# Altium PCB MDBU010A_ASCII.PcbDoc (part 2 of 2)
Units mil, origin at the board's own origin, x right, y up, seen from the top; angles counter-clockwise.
Board outline 3300 x 2500 mil, 2 copper layers (Top Layer, Bottom Layer), stack 64.8 mil thick; 105 components, 70 nets, 307 pads, 460 vias.
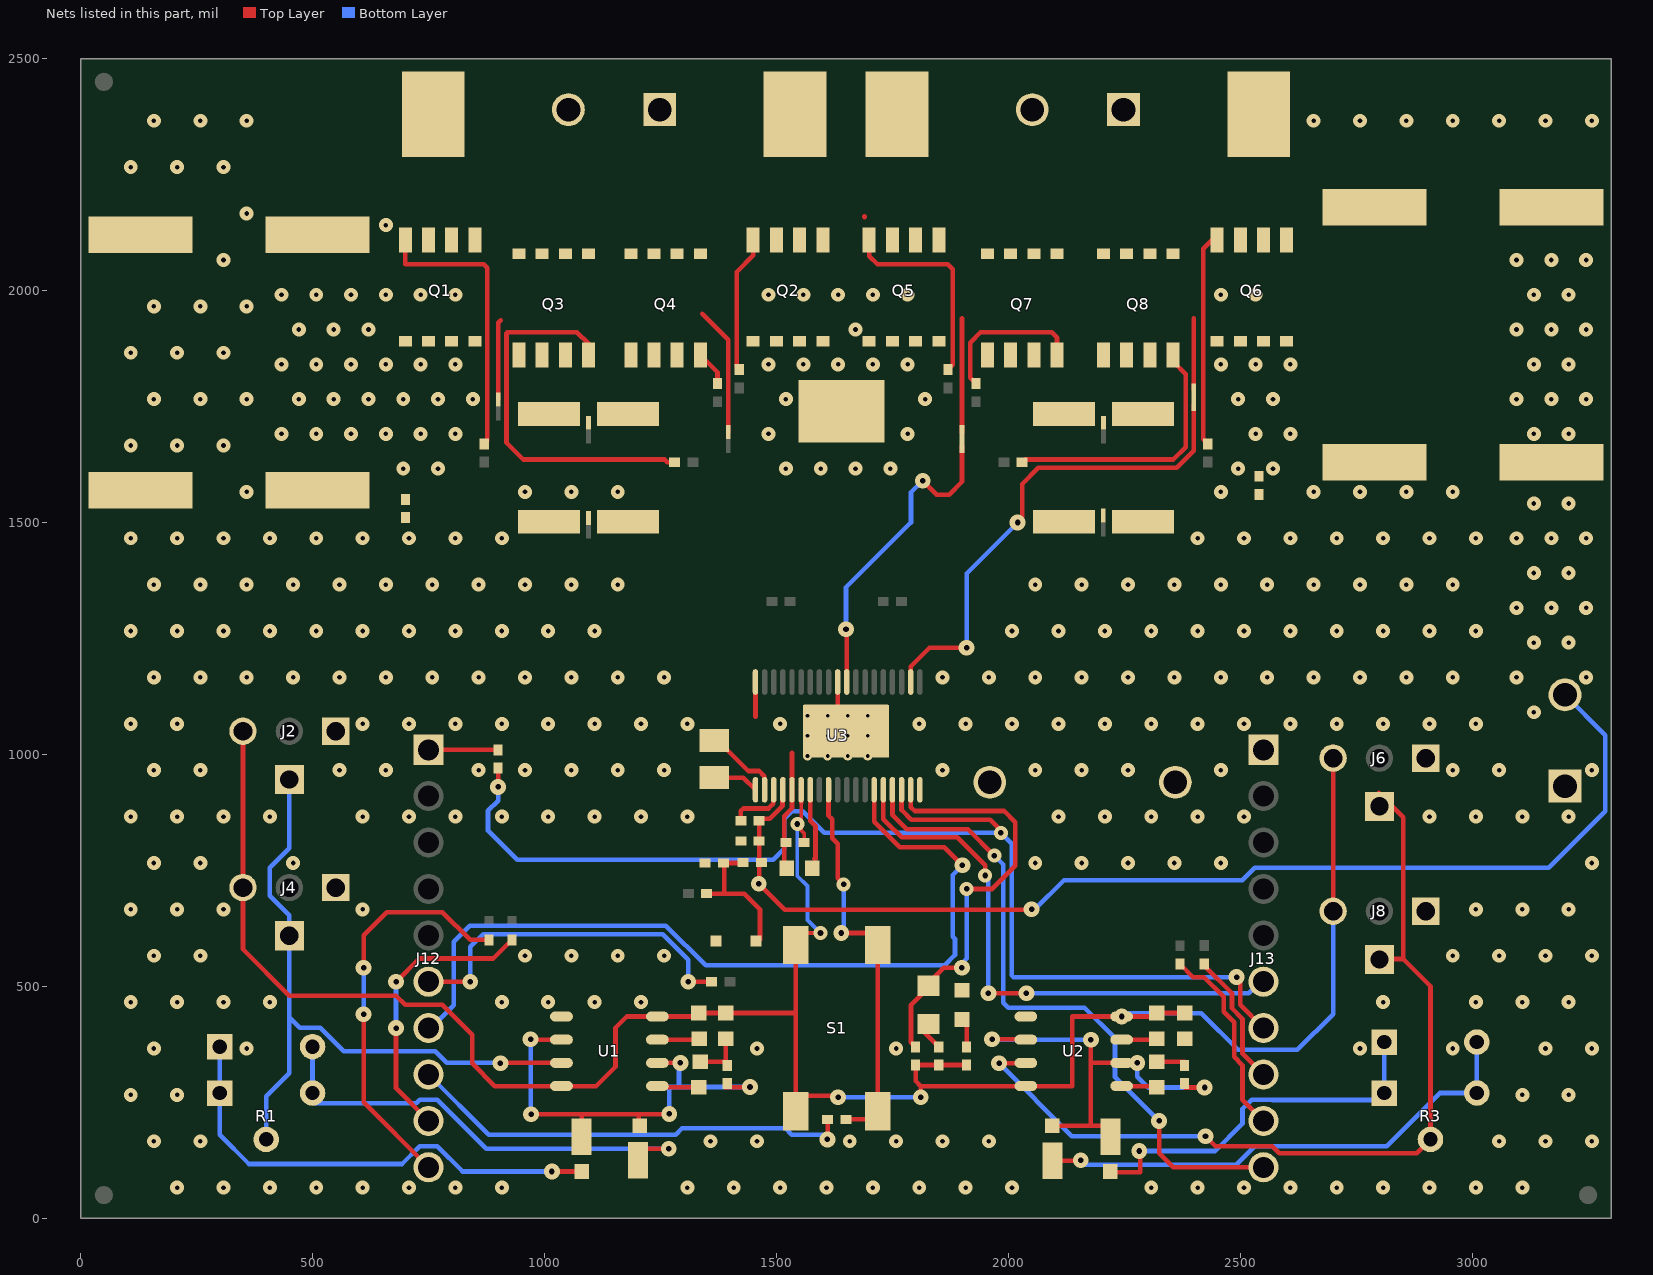
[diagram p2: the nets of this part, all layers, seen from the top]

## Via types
v1: diameter 30, hole 10, Top Layer to Bottom Layer, tented both sides, 357 vias
v2: diameter 34, hole 12, Top Layer to Bottom Layer, 60 vias
v3: diameter 34, hole 12, Top Layer to Bottom Layer, tented top, 20 vias
v4: diameter 20, hole 8, Top Layer to Bottom Layer, 12 vias
v5: diameter 30, hole 12, Top Layer to Bottom Layer, 11 vias

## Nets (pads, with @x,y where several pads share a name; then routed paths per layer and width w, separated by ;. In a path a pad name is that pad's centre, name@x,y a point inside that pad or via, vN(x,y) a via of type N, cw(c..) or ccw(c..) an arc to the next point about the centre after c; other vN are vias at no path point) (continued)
BOUT1: NT3.1 U3.28 | length 686.4
  Top Layer w10: U3.28@1651.68,1156.14 v2@1651.68,1268.32 ; v3(1815.36,1590) 1845.24,1560.13 1872.37,1560.13 1900,1587.75 NT3.1@1900,1665
  Bottom Layer w10: v2(1650,1270) 1650,1360 1790,1500 1790,1564.64 v3(1815.36,1590)
BOUT2: NT4.2 U3.21 | length 1059.2
  Top Layer w10: U3.21@1789.48,1156.14 1789.48,1189.48 1830,1230 v2(1910,1230) ; v3@2030,1510 2030,1583 2064.87,1617.87 2363.15,1617.87 2400,1654.72 NT4.2@2400,1755
  Bottom Layer w10: v2(1910,1230) 1910,1390 v3(2020,1500)
GND: C1.1 C2.1 C3.1 C4.1 C5.1 C6.1 C7.2 C10.1 C11.2 C12.2 C13.2 C14.2 C15.2 C16.2 C17.2 D5.2 D7.1 J2.1 J4.1 J6.1 J8.1 J9.1 J13.1 J14.1 J14.2 NT5.2 NT6.2 R1Sense.1 R2Sense.1 R3Sense.1 R4Sense.1 R7.1 U1.1 U2.1 U3.5 U3.19 U3.29 U3.38 U3.39 | length 587.3
  Top Layer w10: C3.1@1333,337.56 1391,337.56 C1.1@1391,387.44 ; 1454.83,1080.83 U3.38@1454.83,1156.14 ; C7.2@1518.5,755 1517.13,756.38 1517.13,867.13 1533.57,883.57 U3.5@1533.57,923.86 1533.57,1003.57 ; U3.39@1632,1068 U3.29@1632,1156.14 ; C6.1@2320,337.56 C5.1@2380,337.56
  other v1: 208,66 308,66 408,66 508,66 608,66 708,66 808,66 908,66 1308,66 1408,66 1508,66 1608,66 1708,66 1808,66 1908,66 2008,66 2308,66 2408,66 2508,66 2608,66 2708,66 2808,66 2908,66 3008,66 3108,66 158,166 258,166 1358,166 1458,166 1658,166 1758,166 1858,166 1958,166 3058,166 3158,166 3258,166 108,266 208,266 3108,266 3208,266 158,366 358,366 1458,366 1758,366 2758,366 2958,366 3158,366 3258,366 108,466 208,466 308,466 408,466 908,466 1008,466 1108,466 1208,466 2808,466 3008,466 3108,466 3208,466 158,566 258,566 958,566 1058,566 1158,566 1258,566 2958,566 3058,566 3158,566 3258,566 108,666 208,666 308,666 608,666 3008,666 3108,666 3208,666 158,766 258,766 458,766 2058,766 2158,766 2258,766 2358,766 2458,766 3258,766 108,866 208,866 308,866 408,866 608,866 708,866 808,866 908,866 1008,866 1108,866 1208,866 1308,866 2108,866 2208,866 2308,866 2408,866 2508,866 2908,866 3008,866 3108,866 3208,866 158,966 258,966 558,966 658,966 858,966 958,966 1058,966 1158,966 1258,966 1858,966 2058,966 2158,966 2258,966 2458,966 2958,966 3058,966 3258,966 108,1066 208,1066 608,1066 708,1066 808,1066 908,1066 1008,1066 1108,1066 1208,1066 1308,1066 1508,1066 1808,1066 1908,1066 2008,1066 2108,1066 2208,1066 2308,1066 2408,1066 2508,1066 2608,1066 2708,1066 2808,1066 2908,1066 3008,1066 158,1166 258,1166 358,1166 458,1166 558,1166 658,1166 758,1166 858,1166 958,1166 1058,1166 1158,1166 1258,1166 1858,1166 1958,1166 2058,1166 2158,1166 2258,1166 2358,1166 2458,1166 2558,1166 2658,1166 2758,1166 2858,1166 2958,1166 108,1266 208,1266 308,1266 408,1266 508,1266 608,1266 708,1266 808,1266 908,1266 1008,1266 1108,1266 2008,1266 2108,1266 2208,1266 2308,1266 2408,1266 2508,1266 2608,1266 2708,1266 2808,1266 2908,1266 3008,1266 158,1366 258,1366 358,1366 458,1366 558,1366 658,1366 758,1366 858,1366 958,1366 1058,1366 1158,1366 2058,1366 2158,1366 2258,1366 2358,1366 2458,1366 2558,1366 2658,1366 2758,1366 2858,1366 2958,1366 108,1466 208,1466 308,1466 408,1466 508,1466 608,1466 708,1466 808,1466 908,1466 2408,1466 2508,1466 2608,1466 2708,1466 2808,1466 2908,1466 3008,1466 358,1566 958,1566 1058,1566 1158,1566 2458,1566 2658,1566 2758,1566 2858,1566 2958,1566 108,1666 208,1666 308,1666 158,1766 258,1766 358,1766 108,1866 208,1866 308,1866 158,1966 258,1966 358,1966 308,2066 358,2166 108,2266 208,2266 308,2266 158,2366 258,2366 358,2366 2658,2366 2758,2366 2858,2366 2958,2366 3058,2366 3158,2366 3258,2366
  other v4: 1567.04,996.69 1610.35,996.69 1653.65,996.69 1696.96,996.69 1567.04,1040 1610.35,1040 1653.65,1040 1696.96,1040 1567.04,1083.31 1610.35,1083.31 1653.65,1083.31 1696.96,1083.31
MA1: J10.2 NT1.2 Q1.1 Q1.2 Q1.3 Q3.5 Q3.6 Q3.7 Q3.8 TP1.1 | length 173.3
  Top Layer w10: NT1.2@900,1765 900,1930.75 ; 900.28,1931.03 905.62,1936.37
MA2: J10.1 NT2.1 Q2.1 Q2.2 Q2.3 Q4.5 Q4.6 Q4.7 Q4.8 TP2.1 | length 278.4
  Top Layer w10: 1340,1950 1396.39,1893.61 NT2.1@1396.39,1695
MB1: J11.2 NT3.2 Q5.1 Q5.2 Q5.3 Q7.5 Q7.6 Q7.7 Q7.8 TP3.1 | length 246.5
  Top Layer w10: 1690,2158.49 1690,2160 ; NT3.2@1900,1695 1900,1940
MB2: J11.1 NT4.1 Q6.1 Q6.2 Q6.3 Q8.5 Q8.6 Q8.7 Q8.8 TP4.1 | length 155
  Top Layer w10: NT4.1@2400,1785 2400,1940
NetC2_2: C2.2 D1.1 D2.2 U1.2 U1.6 | length 967
  Top Layer w10: v2(970,386) 970,385 U1.2@1036.65,385 ; v2(971,224.21) 1080,224.21 ; D1.1@1080,175.59 1080,224.21 ; D2.2@1203.32,199.21 1203.32,224.21 ; U1.6@1243.35,335 v2@1289,335 ; v2(1269,225) 1269,224.21 1203.32,224.21 ; C2.2@1391,281.95 1391,282.44 v2@1434,282.44 ; 1080,224.21 1203.32,224.21
  Bottom Layer w10: v2(970,386) 970,224.21 v2(971,224.21) ; v2(1269,225) 1269,283 1290,283 ; v2@1290,335 1290,283 ; v2@1434,283 1290,283
  other v2: 1443,283 1293,335
NetC3_2: C3.2 U1.5 | length 86.7
  Top Layer w10: U1.5@1243.35,282.44 C3.2@1330,282.44
NetC5_2: C5.2 D3.1 D4.2 U2.2 U2.6 | length 930.8
  Top Layer w10: v2(1965,386) U2.2@2037.65,386 ; D4.2@2095,199.21 2178,199.21 ; v2(2178,385) 2178,335 ; D3.1@2220,199.21 2178,199.21 ; v2@2281,335 v2(2278,335) U2.6@2244.35,335 2178,335 ; C5.2@2380,282 v2(2423,282) ; 2178,199.21 2178,335
  Bottom Layer w10: v2(1965,386) 1965,385 v2(2178,385) ; v2@2281,335 v2(2278,335) 2278,305.27 2301.27,282 v2(2423,282)
NetC6_2: C6.2 U2.5 | length 73.1
  Top Layer w10: U2.5@2244.35,285 C6.2@2317.44,285
NetC7_1: C7.1 U3.7 | length 156.5
  Top Layer w10: U3.7@1572.94,923.86 1572.94,856.6 1584.37,845.18 1584.37,775 1581.5,775
NetC8_1: C8.1 U3.2 | length 169.7
  Top Layer w10: C8.1@1366,1030 1373.97,1030 1439.68,964.29 1462.61,964.29 1473.61,953.29 U3.2@1473.61,922.95
NetC8_2: C8.2 U3.1 | length 99.7
  Top Layer w10: C8.2@1366,950 1428.69,950 U3.1@1454.83,923.86
NetC9_1: C9.1 U3.3 | length 128.1
  Top Layer w10: C9.1@1423.32,857 1423.32,878.32 1428.43,883.43 1482.8,883.43 1493.3,893.93 1493.3,922.95 U3.3@1494.2,923.86
NetD1_2: D1.2 pad.0@300,370 R1.1 | length 1034.6
  Top Layer w10: v2(1016,100.79) D1.2@1080,100.79
  Bottom Layer w10: pad.0@300,370 R1.1@300,270 300,180 363,117 692.86,117 731.21,155.35 768.79,155.35 823.35,100.79 v2(1016,100.79)
NetD2_1: D2.1 pad.1@500,370 R1.3 | length 978.7
  Top Layer w10: D2.1@1200,150 v2(1268,150)
  Bottom Layer w10: R1.3@500,270 pad.1@500,370 ; R1.3@504,248 723.86,248 731.21,255.35 768.79,255.35 874.14,150 v2(1268,150)
NetD3_2: D3.2 pad.0@2810,380 R3.1 | length 797.4
  Top Layer w10: D3.2@2220,100.79 2220,99 2284,99 v2@2284,143
  Bottom Layer w10: v2(2282,145) 2446,145 2504.65,203.65 2504.65,235.65 2524.35,255.35 2568.79,255.35 2569.14,255 R3.1@2795,255 ; R3.1@2810,270 pad.0@2810,380
NetD4_1: D4.1 pad.1@3010,380 R3.3 | length 1099.6
  Top Layer w10: D4.1@2095,124.41 2156,124.41 v2(2156,125)
  Bottom Layer w10: v2(2156,125) 2156,115.13 2490.99,115.13 2531.21,155.35 2815.35,155.35 2930,270 R3.3@3010,270 pad.1@3010,380
NetD5_1: D5.1 R6.1 R7.2 R22.2 | length 301.8
  Top Layer w10: R22.2@1349.69,700 1387.65,700 ; R6.1@1429.28,766 1387.65,766 1387.65,700 ; D5.1@1464.47,601 1464.47,666.56 1431.03,700 1387.65,700
NetD6_1: D6.1 R23.1 U3.18 | length 911.8
  Top Layer w10: U3.18@1789.48,923.86 1789.48,886.52 1798,878 1991,878 2015,854 2015,760 1965,710 v5(1910,710) ; R23.1@1800,369.68 1790,379.68 1790,459.53 D6.1@1820,489.53 ; D6.1@1815,494.53 1860.47,540 v2(1900,540)
  Bottom Layer w10: v2(1900,540) 1900,550 1910,560 v5(1910,710) v5@1909,709
NetD6_2: D6.2 R5.2 | length 73.2
  Top Layer w10: D6.2@1820,430.47 1820,399.69 R5.2@1850,369.69
NetD7_2: D7.2 R16.1 | length 48.8
  Top Layer w10: R16.1@1910,369.68 D7.2@1910,418.5
NetJ12_6: J12.6 R21.1 | length 767
  Top Layer w10: J12.6@750,510 v3(840,510) ; v2(1310,510) R21.1@1360.32,510
  Bottom Layer w10: v3(840,510) 840,584.94 867.71,612.64 1254.8,612.64 1310,557.44 v2(1310,510)
NetJ12_8: J12.8 R26.1 | length 958.1
  Top Layer w10: v2@1610.31,180.31 R26.1@1610.31,213.14
  Bottom Layer w10: J12.8@750,310 879.69,180.31 1282.89,180.31 1296.45,193.87 1519.55,193.87 1533.11,180.31 v2@1610.31,180.31
  other v2: 1610,170
NetJ12_9: J12.9 R17.1 | length 616.4
  Top Layer w10: v2(680,410) 680,280 J12.9@750,210 ; v2(680,510) 730,560 889.68,560 R17.1@930,600.32
  Bottom Layer w10: v2(680,410) v2(680,510)
NetJ12_10: J12.10 R18.1 | length 873.4
  Top Layer w10: v2(610,440) 610,250 J12.10@750,110 ; v2(610,540) 610,610 660,660 780,660 839.68,600.32 R18.1@880,600.32
  Bottom Layer w10: v2(610,440) v2(610,540)
NetJ13_8: J13.8 R20.1 | length 291.4
  Top Layer w10: R20.1@2422.28,548.49 2422.28,544.84 2482.13,485 2482.13,452.6 2504.65,430.08 2504.65,355.35 J13.8@2550,310
NetJ13_9: J13.9 R19.1 | length 426.6
  Top Layer w10: R19.1@2370,548.13 2398.13,520 2421.85,520 2464.25,477.6 2464.25,445.19 2486.77,422.67 2486.77,347.95 2504.65,330.08 2504.65,255.35 J13.9@2550,210
NetNT7_2: NT7.2 Q7.1 Q7.2 Q7.3 Q8.1 Q8.2 Q8.3 R3Sense.2 R4Sense.2
NetNT8_2: NT8.2 Q3.1 Q3.2 Q3.3 Q4.1 Q4.2 Q4.3 R1Sense.2 R2Sense.2
NetQ1_4: Q1.4 R8.2 | length 614.9
  Top Layer w10: Q1.4@700,2109.3 700,2056.43 869.31,2056.43 876.85,2048.89 876.85,1676.54 R8.2@870,1669.69
NetQ2_4: Q2.4 R9.1 | length 288.7
  Top Layer w10: R9.1@1414.26,1835.42 1414.26,2040 1450,2075.74 Q2.4@1450,2109.3
NetQ3_4: Q3.4 R10.2 | length 828.1
  Top Layer w10: Q3.4@1095,1860.7 1095,1885 1070,1910 920,1910 918.15,1908.15 918.15,1671.85 954.25,1635.75 1258.82,1635.75 1264.57,1630 R10.2@1280.31,1630
NetQ4_4: Q4.4 R11.1 | length 76.3
  Top Layer w10: Q4.4@1336,1860.7 1373,1823.7 R11.1@1373,1799.68
NetQ5_4: Q5.4 R12.2 | length 447
  Top Layer w10: Q5.4@1700,2109.3 1700,2074.3 1717.87,2056.43 1869.31,2056.43 1880,2045.74 1880,1839.69 R12.2@1870,1829.69
NetQ6_4: Q6.4 R13.1 | length 462.5
  Top Layer w10: R13.1@2430,1669.68 2420,1679.68 2420,2090 2439.3,2109.3 Q6.4@2450,2109.3
NetQ7_4: Q7.4 R14.2 | length 332.1
  Top Layer w10: R14.2@1930,1799.69 1917.87,1811.81 1917.87,1887.87 1940,1910 2093.57,1910 2105,1898.57 Q7.4@2105,1860.7
NetQ8_4: Q8.4 R15.1 | length 575.6
  Top Layer w10: R15.1@2029.68,1630 2035.43,1635.75 2355.75,1635.75 2382.13,1662.13 2382.13,1820 2355,1847.13 Q8.4@2355,1860.7
NetR2_1: R2.1 U1.7 | length 90
  Top Layer w10: U1.7@1243.35,385 R2.1@1333.32,385
NetR4_1: R4.1 U2.7 | length 73.2
  Top Layer w10: U2.7@2244.35,385 R4.1@2317.56,385
RESET: R26.2 S1.3 S1.4 U3.9 | length 793.6
  Top Layer w10: U3.9@1612.31,923.86 1612.31,867.79 1620.12,859.98 1620.12,819.23 1631.93,807.42 1631.93,733.07 v5(1645,720) ; v2(1640,615) 1710.43,615 1718.58,606.85 S1.4@1718.58,589.13 S1.3@1718.58,270.87 ; R26.2@1649.68,213.14 S1.3@1700.86,213.14
  Bottom Layer w10: v2(1640,615) 1645,620 v5(1645,720)
SCLK: J12.7 U3.14 | length 1853.6
  Top Layer w10: U3.14@1710.74,923.86 1710.74,855 1721.3,844.44 ; 1721.3,844.42 1765.72,800 1862,800 v2(1901,761)
  Bottom Layer w10: J12.7@750,410 755,410 804,459 804,596 839,631 1261.72,631 1347.47,545.25 1862.5,545.25 1884.87,567.63 1884.87,602.25 1880,607.12 1880,740 v2(1901,761)
SCS: J13.10 U3.16 | length 1417
  Top Layer w10: U3.16@1750.11,923.86 1750.11,869.89 1781,839 1913,839 v5(1970,782) ; v3(2325,210) 2325,140.13 2355.13,110 J13.10@2550,110
  Bottom Layer w10: v5(1970,782) 1989.25,762.75 1989.25,464.47 1999.72,454 2164.12,454 2230,388.12 2230,304 v3@2313,221
SDATI: J13.6 U3.15 | length 1206.4
  Top Layer w10: U3.15@1730.43,923.86 1730.43,860.59 1739.17,851.84 1769.87,821.13 1889.87,821.13 1950,761 v5(1950,739) ; v3(1957,485) v3(2039,485)
  Bottom Layer w10: v5(1950,739) 1957,732 v3(1957,485) ; v3(2039,485) 2518.01,485 2543.01,510 J13.6@2550,510
SDATO: J13.7 R24.1 U3.17 | length 2595.8
  Top Layer w10: v2(900,930) R24.1@900,970.32 ; U3.17@1769.8,923.86 1769.8,880.2 1791,859 1961,859 v5@1990,830 ; v2@2496,520 2500,516 2500,460 J13.7@2550,410
  Bottom Layer w10: v2(900,930) 900,900.25 878.13,878.37 878.13,836.13 941.02,773.23 1493.23,773.23 1517.13,797.13 1517.13,861.55 1533.45,877.87 1556.55,877.87 1603.42,831 v5(1984,831) 2007.13,807.87 2007.13,524 2011.13,520 v2(2492,520)
TLC555_OUT_1: J1.1 J3.1 R1.2 U1.3 | length 1459.1
  Top Layer w10: v2@906,335 U1.3@1036.65,335
  Bottom Layer w10: R1.2@400,170 400,263 450,313 450,433 ; J1.1@450,947 450,797.8 407.6,755.4 407.6,695.44 450,653.04 450,610 450,433 ; v2@905,335 789.14,335 764.14,360 567.1,360 516.72,410.37 472.63,410.37 450,433
  other v2: 905,334
TLC555_OUT_2: J5.1 J7.1 R3.2 U2.3 | length 1923.7
  Top Layer w10: v2(1980,334) U2.3@2036.65,334 ; v2(2425,177) 2446.65,155.35 2568.79,155.35 2584.14,140 2880,140 R3.2@2910,170 2910,500 2851.02,558.98 ; J5.1@2798.16,917.01 2851.02,864.15 2851.02,558.98 ; J7.1@2800.05,558.98 2851.02,558.98
  Bottom Layer w10: v2(1980,334) 2137,177 v2(2425,177)
V3.3: J12.1 R24.2 | length 149.7
  Top Layer w10: J12.1@750,1010 R24.2@899.69,1010
V5: C1.2 C4.2 C11.1 J2.3 J4.3 J6.3 J8.3 R2.2 R4.2 R5.1 R16.2 R23.2 S1.1 S1.2 U1.4 U1.8 U2.4 U2.8 U3.6 | length 4947.2
  Top Layer w8: S1.2@1541.42,589.13 1567.28,615 v5(1595,615) ; 1553.26,895.33 1553.26,836.43 1559.68,830 C11.1@1559.68,810
  Top Layer w10: J2.3@350,1050 J4.3@350,713 350,580 449.87,480.13 679.87,480.13 700,460 780,460 844,396 844,334 893,285 U1.4@1036.65,285 1111,285 1153.13,327.13 1153.13,411.13 1177,435 U1.8@1243.35,435 R2.2@1333,435 ; R2.2@1333,442.56 C1.2@1391,442.56 1541.42,442.56 ; S1.1@1541.42,270.87 1541.42,442.56 ; S1.2@1541.42,589.13 1541.42,442.56 ; S1.1@1548.28,264 v3@1630,264 ; U3.6@1552.94,923.54 U3.6@1553.26,923.86 1553.26,895.33 ; v2@1810,260 v2(1811,261) 1811,285 ; R16.2@1910,330.31 R5.1@1850,330.32 R23.2@1800,330.31 1800,296 1811,285 ; C4.2@2380,442.56 R4.2@2320,442.56 2312.44,435 v2(2244.35,435) 2138,435 2138,285 U2.4@2037.65,285 1811,285 ; J8.3@2700.05,661.98 J6.3@2700.05,1016
  Bottom Layer w8: v5(1545,850) 1545,738.01 1566.87,716.13 1566.87,643.13 v5(1595,615)
  Bottom Layer w10: v3@1630,264 v3(1633,261) v2(1811,261) ; v2@2251.35,442 2416,442 2495,363 2623,363 2700.05,440.05 J8.3@2700.05,661.98
VM: C9.2 C10.2 C12.1 C13.1 C14.1 C15.1 C16.1 C17.1 J9.2 Q1.5 Q1.6 Q1.7 Q1.8 Q2.5 Q2.6 Q2.7 Q2.8 Q5.5 Q5.6 Q5.7 Q5.8 Q6.5 Q6.6 Q6.7 Q6.8 R6.2 U3.4 VM.1 | length 2442.7
  Top Layer w10: v2(1462,721) 1518,665 v2@2035,665 ; v2@1462.69,721.69 C10.2@1462.69,813 C9.2@1462.69,857 1466.69,861 1485.65,861 1512.98,888.33 1512.98,922.95 U3.4@1513.89,923.86
  Bottom Layer w10: v2(2050,666) 2057.21,666 2120,728.79 2504.65,728.79 2531.21,755.35 3165.35,755.35 3287.13,877.13 3287.13,1041.3 J9.2@3200,1128.43
  other v1: 3133,1091 3095.5,1166 3245.5,1166 3133,1241 3208,1241 3095.5,1316 3170.5,1316 3245.5,1316 3133,1391 3208,1391 3095.5,1466 3170.5,1466 3245.5,1466 3133,1541 3208,1541 695.5,1616 770.5,1616 1520.5,1616 1595.5,1616 1670.5,1616 1745.5,1616 2495.5,1616 2570.5,1616 433,1691 508,1691 583,1691 658,1691 733,1691 808,1691 1483,1691 1783,1691 2533,1691 2608,1691 3133,1691 3208,1691 470.5,1766 545.5,1766 620.5,1766 695.5,1766 770.5,1766 845.5,1766 1520.5,1766 1820.5,1766 2495.5,1766 2570.5,1766 3095.5,1766 3170.5,1766 3245.5,1766 433,1841 508,1841 583,1841 658,1841 733,1841 808,1841 1483,1841 1558,1841 1633,1841 1708,1841 1783,1841 2458,1841 2533,1841 2608,1841 3133,1841 3208,1841 470.5,1916 545.5,1916 620.5,1916 1670.5,1916 3095.5,1916 3170.5,1916 3245.5,1916 433,1991 508,1991 583,1991 658,1991 733,1991 808,1991 1483,1991 1558,1991 1633,1991 1708,1991 1783,1991 2458,1991 2533,1991 3133,1991 3208,1991 3095.5,2066 3170.5,2066 3245.5,2066 658,2141
pads on no net: FID1.1 FID2.1 FID3.1 J12.2 J12.3 J12.4 J12.5 J13.2 J13.3 J13.4 J13.5 U3.20

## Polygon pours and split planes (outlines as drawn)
GND on Top Layer "Top Layer-No Net" (solid, remove dead copper, pour order 17): 20,20 20,2480 3280,2480 3280,20 20,20
VM on Top Layer "VM" (solid, remove dead copper, pour order 26): 2420,1900 2420,1590 2630,1590 2630,1900 2420,1900
VM on Top Layer "VM" (solid, remove dead copper, pour order 24): 1430,2040 1430,1590 1865,1590 1865,2040
VM on Top Layer "VM" (solid, remove dead copper, pour order 23): 3060,2250 3060,1040 3280,1040 3280,2250 3060,2250
VM on Top Layer "VM" (solid, remove dead copper, pour order 21): 400,2480 685,2480 685,2050 863.98,2050 863.98,1530 860,1530 400,1530 400,2479.68
MA1 on Top Layer "MA1" (solid, remove dead copper, pour order 22): 1120,2480 685,2480 685,1930 1120,1930
MA2 on Top Layer "MA2" (solid, remove dead copper, pour order 19): 1160,2480 1615,2480 1615,1930 1160,1930
MB1 on Top Layer "MB1" (solid, remove dead copper, pour order 18): 2140,2480 1685,2480 1685,1930 2140,1930
MB2 on Top Layer "MB2" (solid, remove dead copper, pour order 15): 2180,2480 2615,2480 2615,1930 2180,1930
NetNT8_2 on Top Layer "AISENP" (solid, remove dead copper, pour order 27): 926.54,1892.43 926.54,1662.43 1366,1662.43 1366,1892.43 926.54,1892.43
NetNT7_2 on Top Layer "BISENP" (solid, remove dead copper, pour order 25): 1938,1892.13 1938,1662.13 2378,1662.13 2378,1892.13 1938,1892.13
GND on Bottom Layer "GND" (solid, remove dead copper, pour order 20): 20,20 20,2480 3280,2480 3280,20 20,20
VM on Bottom Layer "VM" (solid, remove dead copper, pour order 16): 3060,2250 3280,2250 3280,1040 3060,1040 3060,2250
VM on Bottom Layer "VM" (solid, remove dead copper, pour order 28): 400,2250 400,1590 3280,1590 3280,2250

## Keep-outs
Keep-Out Layer:
  lines w10: -5,0 ccw(c0,0) 0,-5 ; -5,0 ccw(c0,0) 0,-5 ; -5,0 ccw(c0,0) 0,-5 ; -5,0 ccw(c0,0) 0,-5 ; -5,0 -5,2500 ; -5,2500 cw(c0,2500) 0,2505 ; -5,2500 cw(c0,2500) 0,2505 ; 0,-5 3300,-5 ; 0,-5 3300,-5 ; 0,2505 3300,2505 ; 3300,-5 ccw(c3300,0) 3305,0 ; 3300,-5 ccw(c3300,0) 3305,0 ; 3300,-5 ccw(c3300,0) 3305,0 ; 3300,-5 ccw(c3300,0) 3305,0 ; 3300,2505 cw(c3300,2500) 3305,2500 ; 3300,2505 cw(c3300,2500) 3305,2500 ; 3305,0 3305,2500
  text ".Layer_Name" at 577,-858.49 h60

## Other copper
Top Layer:
  rectangle net GND: 1804,895 2074,1017
  rectangle net GND: 1536,997 1639,1051
  text ".Layer_Name" at 577,-858.49 h60
Bottom Layer:
  text ".Layer_Name" at 577,-858.49 h60

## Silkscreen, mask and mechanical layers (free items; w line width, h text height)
Top Overlay:
  lines w3: 802,507 885,507
  lines w4: 1756,420 1756,532
  lines w5: 1265,1560 2035,1560 ; 1270,1370 1270,1300 1320,1250 ; 1320,1370 1320,1320 1350,1290 ; 1370,1370 1370,1350 1400,1320 ; 1420,1370 1420,1350 1455,1315 ; 1470,1370 1470,1350 1473,1347 ; 1508,1312 1525,1295 ; 1520,1370 1520,1350 1522,1348 ; 1570,1325 1590,1310 1590,1296 ; 1570,1365 1570,1370 ; 1619.87,1326 1619.87,1369.87 ; 1650,1296 1650,1310 1670,1325 ; 1670,1365 1670,1370 ; 1695,1325 1710,1340 ; 1710,1296 1710,1300 1712,1302 ; 1720,1350 1720,1370 ; 1760,1350 1770,1360 1770,1370 ; 1780,1297.88 1822.12,1340 1840,1340 1870,1370 ; 1790,1340 1820,1370 ; 1848,1300 1850,1300 1920,1370 ; 1890,1290 1970,1370 ; 1910,1256 1910,1260 2020,1370
  lines w10: 180,830 702,830 ; 2600,770 3045.35,770
  text "MA1" at 690,2180 h100
  text "MA2" at 1430,2180 h100
  text "MB1" at 1690,2180 h100
  text "MB2" at 2430,2180 h100
  text "Motor A" at 990,2110 h100
  text "Motor B" at 2000,2110 h100
  text "Test Point Vias" at 1520,1570 h40
  text "AOUT1" at 1290,1380 h50 r90
  text "A1HS" at 1340,1380 h50 r90
  text "A1LS" at 1390,1380 h52 r90
  text "AISENP" at 1440,1380 h50 r90
  text "AISENN" at 1490,1380 h50 r90
  text "A2LS" at 1540,1380 h50 r90
  text "A2HS" at 1590,1380 h50 r90
  text "AOUT2" at 1640,1380 h50 r90
  text "BOUT1" at 1690,1380 h50 r90
  text "B1HS" at 1740,1380 h50 r90
  text "B1LS" at 1790,1380 h50 r90
  text "BISENP" at 1840,1380 h50 r90
  text "BISENN" at 1890,1380 h50 r90
  text "B2LS" at 1940,1380 h50 r90
  text "B2HS" at 1990,1380 h50 r90
  text "BOUT2" at 2040,1380 h50 r90
  text "VM" at 3160,1260 h60
  text ".PRJ_Number" at 2430,1210 h60
  text ".PCB_Rev" at 2700,1210 h60
  text "AIN1" at 400,1120 h50
  text "BIN1" at 2750,1060 h50
  text "HIGH" at 180,1050 h50
  text "LOW" at 610,1050 h50
  text "HIGH" at 2598,1050 h50
  text "LOW" at 2900,1050 h50
  text "DRV8704EVM" at 1890,1020 h60
  text "VCC" at 798,980 h30
  text "GND" at 2450,980 h30
  text "GND" at 2300,860 h60
  text "PWM" at 400,850 h50
  text "PWM" at 2750,790 h50
  text "AIN2" at 400,770 h50
  text "GND" at 3140,740 h60
  text "BIN2" at 2750.05,725.11 h50
  text "HIGH" at 2598,720 h50
  text "LOW" at 2900,720 h50
  text "HIGH" at 180,710 h50
  text "LOW" at 610,710 h50
  text "PWM" at 2870,530 h50
  text "PWM" at 400,520 h50
  text "SLEEP" at 800,480 h30
  text "SDATI" at 2400,480 h30
  text "FAULT" at 1790,419.61 h40 r90
  text "STATUS" at 1953.32,415 h40 r90
  text "SCLK" at 800,380 h30
  text "SDATO" at 2410,380 h30
  text "RESET" at 800,280 h30
  text "BIN1" at 2450,280 h30
  text "BIN2" at 2449.52,181.22 h30
  text "AIN1" at 800,180 h30
  text "SPEED" at 3130,150 h50
  text "SPEED" at 40,100 h50
  text "RESET" at 1516,90 h80
  text "AIN2" at 800,80 h30
  text "SCS" at 2450,80 h30
  text "Motor A Control" at 170,20 h80
  text "Motor B Control" at 2660,20 h80
  text ".Layer_Name" at 577,-858.49 h60
Bottom Overlay:
  text ".Layer_Name" at 577,-858.49 h60
Top Paste:
  text ".Layer_Name" at 577,-858.49 h60
Bottom Paste:
  text ".Layer_Name" at 577,-858.49 h60
Top Solder:
  text ".Layer_Name" at 577,-858.49 h60
  text ".Layer_Name" at 577,-858.49 h60
Bottom Solder:
  text ".Layer_Name" at 577,-858.49 h60
Drill Guide:
  text ".Layer_Name" at 577,-858.49 h60
M1 Board Outline:
  the board outline again, w10
  text ".Layer_Name" at 577,-858.49 h60
M2 Board Dimensions:
  rectangle: 125,-400 500,-275
  rectangle: 0,-275 125,-150
  lines w7: 0,-275 1000,-275 ; 125,-400 125,-150 ; 250,-400 250,-150 ; 500,-400 500,-150 ; 750,-400 750,-150 ; 0,-400 0,-150 1000,-150 1000,-400 0,-400
  text ".Layer_Name" at 577,-858.49 h60
M3 3D STEP Top:
  text ".Layer_Name" at 577,-858.49 h60
M4 3D STEP Bottom:
  text ".Layer_Name" at 577,-858.49 h60
M5 Assembly Top:
  lines w10: -292,-930.17 6308,-930.17 ; -292,-726.83 6310,-726.83 ; -292,-523.5 -292,-1133.5 3713,-1133.5 6310,-1133.5 6310,-523.5 -291.5,-523.5 -291.5,-1133.5 1284,-1133.5 ; 2173,-1133.5 2173,-523.5 ; 3440,-726.83 3440,-523.5 ; 4280,-726.83 4280,-523.5 ; 4902,-1140 4902,-937.17
  text "COMPONENTS MARKED 'DNP' SHOULD NOT BE POPULATED." at 1153.5,-318.5 h60
  text "ASSEMBLY VARIANT:" at 1153,-434 h60
  text ".VariantName" at 2189,-434 h60
  text "PCB VIEWED FROM TOP SIDE" at -228.5,-655.67 h60
  text "BOARD #:" at 2248,-655.67 h60
  text ".PRJ_Number" at 2793.5,-655.67 h60
  text "REV:" at 3638,-655.67 h60
  text ".PCB_Rev" at 3929.5,-655.67 h60
  text "SVN REV:" at 4476,-655.67 h60
  text ".VersionControl_RevNumber" at 4982,-655.67 h60
  text "TID #:" at 2248,-859 h60
  text ".TID" at 2793.5,-859 h60
  text "PLOT NAME =" at -228.5,-1064.34 h60
  text ".plot_File_Name" at 577,-1064.34 h60
  text "GENERATED    :" at 2250,-1064.34 h60
  text ".Print_Date" at 3119.5,-1064.34 h60
  text ".Print_Time" at 3848.5,-1064.34 h60
  text "TEXAS INSTRUMENTS" at 5113,-1064.34 h60
M6 Assembly Bottom:
  lines w10: -292.5,-727.33 6309.5,-727.33 ; -290.5,-930.67 6309.5,-930.67 ; 1115.5,-1140.5 1115.5,-937.67 ; 1737.5,-727.33 1737.5,-524 ; 2577.5,-727.33 2577.5,-524 ; 3844.5,-1134 3844.5,-524 ; 4733.5,-1134 6309,-1134 6309,-524 -292.5,-524 -292.5,-1134 2304.5,-1134 6309.5,-1134 6309.5,-524
  text "COMPONENTS MARKED 'DNP' SHOULD NOT BE POPULATED." at 6102,-318 h60
  text ".VariantName" at 5058,-434 h60
  text "ASSEMBLY VARIANT:" at 6097,-434 h60
  text ".VersionControl_RevNumber" at 1035.5,-656.17 h60
  text "SVN REV:" at 1541.5,-656.17 h60
  text ".PCB_Rev" at 2088,-656.17 h60
  text "REV:" at 2379.5,-656.17 h60
  text ".PRJ_Number" at 3224,-656.17 h60
  text "BOARD #:" at 3769.5,-656.17 h60
  text "PCB VIEWED FROM BOTTOM SIDE" at 6246,-656.17 h60
  text ".TID" at 3224,-859.5 h60
  text "TID #:" at 3769.5,-859.5 h60
  text "TEXAS INSTRUMENTS" at 904.5,-1064.84 h60
  text ".Print_Time" at 2169,-1064.84 h60
  text ".Print_Date" at 2898,-1064.84 h60
  text "GENERATED    :" at 3767.5,-1064.84 h60
  text ".plot_File_Name" at 5440.5,-1064.84 h60
  text "PLOT NAME =" at 6246,-1064.84 h60
M9 Title Sheet:
  lines w10: -491.5,1041.5 -291.5,1041.5 ; -491.5,3416.5 -291.5,3416.5 ; -491.5,5791.5 -291.5,5791.5 ; 2008.5,-1333.5 2008.5,-1133.5 ; 2008.5,7966.5 2008.5,8166.5 ; 4508.5,-1333.5 4508.5,-1133.5 ; 4508.5,7966.5 4508.5,8166.5 ; 6321,-1133.5 6321,-523.5 11303.5,-523.5 ; 7008.5,-1333.5 7008.5,-1133.5 ; 7008.5,7966.5 7008.5,8166.5 ; 9508.5,-1333.5 9508.5,-1133.5 ; 9508.5,7966.5 9508.5,8166.5 ; 11303.5,-1133.5 11303.5,-523.5 ; 11303.5,-823.5 14303.5,-823.5 ; 11303.5,-223.5 14303.5,-223.5 ; 11304.5,370.5 14304.5,370.5 ; 12008.5,-1333.5 12008.5,-1133.5 ; 12008.5,7966.5 12008.5,8166.5 ; 12808.5,-1123.5 12808.5,-523.5 ; 14303.5,-523.5 11303.5,-523.5 ; 14303.5,76.5 11303.5,76.5 ; 14308.5,66.5 14308.5,-1133.5 ; 14308.5,871 11304.5,871 11303.5,871 11303.5,370.5 11303.5,76.5 ; 14308.5,1041.5 14508.5,1041.5 ; 14308.5,3416.5 14508.5,3416.5 ; 14308.5,5791.5 14508.5,5791.5 ; 11303.5,-523.5 11303.5,76.5 ; 14308.5,-1133.5 -291.5,-1133.5 -291.5,7966.5 14308.5,7966.5 14308.5,-1133.5 ; -491.5,-1333.5 14508.5,-1333.5 14508.5,8166.5 -491.5,8166.5 -491.5,-1333.5
  text "1" at 739.84,8036.5 h70
  text "2" at 3235.5,8036.5 h70
  text "3" at 5724.84,8036.5 h70
  text "4" at 8231.51,8036.5 h70
  text "5" at 10730.5,8036.5 h70
  text "6" at 13235.5,8036.5 h70
  text "A" at -416.5,6893.5 h70
  text "A" at 14383.5,6893.5 h70
  text "B" at -416.5,4513.5 h70
  text "B" at 14383.5,4513.5 h70
  text "C" at -416.5,2138.5 h70
  text "C" at 14383.5,2138.5 h70
  text "PROJECT TITLE:" at 11343.5,277.5 h45
  text ".PRJ_Title" at 11393.5,144.17 h70
  text "DESIGNED FOR:" at 11343.5,-23.5 h45
  text ".PRJ_Customer" at 11393.5,-163.5 h70
  text "D" at -416.5,-231.5 h70
  text "D" at 14383.5,-231.5 h70
  text "FILE NAME:" at 11343.5,-323.5 h45
  text ".PCB_File_Name_No_Path" at 11393.5,-443.5 h70
  text "Texas Instruments (TI) and/or its licensors do not warrant the accuracy or completeness of this specification" at 6374,-605.34 h45
  text "ENGINEER:" at 11343.5,-613.5 h45
  text "LAYOUT BY:" at 12848.5,-613.5 h45
  text "or any information contained therein. TI and/or its licensors do not warrant that this design will meet" at 6329.01,-718 h45
  text ".PRJ_Engineer" at 11393.5,-768.49 h70
  text ".PCB_Layout" at 12899,-768.49 h70
  text "the specifications, will be suitable for your application or fit for any particular purpose, or will operate in" at 6329.01,-830.67 h45
  text ".Layer_Name" at 577,-858.49 h60
  text "ALTIUM DESIGNER VERSION:" at 12848.5,-923.5 h45
  text "an implementation. TI and/or its licensors do not warrant that the design is production worthy. You should" at 6329.01,-943.33 h45
  text "completely validate and test your design implementation to confirm the system functionality for your application." at 6374,-1056 h45
  text ".print_Scale" at 11393.5,-1056.83 h70
  text ".Application_BuildNumber" at 12899,-1056.83 h70
  text "1" at 739.84,-1263.5 h70
  text "2" at 3235.5,-1263.5 h70
  text "3" at 5724.84,-1263.5 h70
  text "4" at 8231.51,-1263.5 h70
  text "5" at 10730.5,-1263.5 h70
  text "6" at 13235.5,-1263.5 h70
M10 Fab Notes:
  drawing of 185 lines, arcs and shapes, not listed
  text "DESIGN INFORMATION" at 12381.02,5910 h60
  text "MIN. TRACK WIDTH:" at 11736.46,5730 h60
  text "8" at 12832.7,5730 h60
  text "MIL" at 12987.46,5730 h60
  text "MIN. CLEARANCE:" at 11736.46,5598 h60
  text "0.2" at 12772.7,5598 h60
  text "mm" at 12987.46,5598 h60
  text "MIN. VIA PAD SIZE:" at 11736.46,5466 h60
  text "24" at 12802.71,5466 h60
  text "MIL" at 12987.46,5466 h60
  text "0.05mm (2MIL)" at 12431.46,5324.29 h60
  text "MINIMUM ANNULAR RING" at 11407.23,5320 h60
  text "EXTERNAL" at 13139.46,5320 h60
  text "PER" at 11607.23,5202 h60
  text "IPC-D-275 CLASS 2 LEVEL C" at 11827.23,5202 h60
  text "MIL, HOLES" at 13315.46,5089.71 h60
  text "+/-" at 12923,5089 h60
  text "+/-" at 13777,5089 h60
  text "REGISTRATION TOLERANCES:" at 11407.23,5084 h60
  text "METAL" at 12607,5084 h60
  text "5" at 13183.2,5084 h60
  text "3" at 14016.2,5084 h60
  text "MIL" at 14132.46,5084 h60
  text "MATERIAL:" at 11332.46,4874.54 h60
  text "FR-4 High Tg" at 12318.9,4734.21 h60
  text "FR-408" at 11753.46,4725.64 h60
  text "X" at 12165.46,4725.64 h60
  text "OTHER" at 13241.46,4725.64 h60
  text "62 MIL (1.6mm) +/-10%" at 12073.56,4562.92 h60
  text "THICKNESS:" at 11407.23,4558.64 h60
  text "X" at 11945.4,4558.64 h60
  text "OTHER" at 13358.46,4558.64 h60
  text "TOLERANCE:" at 11407.23,4400.64 h60
  text "X" at 12246.53,4400.64 h60
  text "ANSI IPC-6012 TYPE 3 CLASS 2" at 12433.48,4400.64 h60
  text "OTHER +/-" at 12433.46,4244.64 h60
  text "BOW & TWIST:" at 11407.23,4087.64 h60
  text "X" at 12246.53,4087.64 h60
  text "ANSI IPC-6012 TYPE 3 CLASS 2" at 12433.48,4087.64 h60
  text "OTHER +/-" at 12433.46,3929.13 h60
  text "DRILLING:" at 11332.46,3790.64 h60
  text "REFERENCE:" at 11407.23,3673.64 h60
  text "X" at 12055.46,3673.64 h60
  text "AS SHOWN" at 12242.46,3673.64 h60
  text "X" at 12956.46,3673.64 h60
  text "NC_DRILL FILES" at 13093.46,3673.64 h60
  text "PTH MIN COPPER THICKNESS:" at 11407.23,3515.64 h60
  text "1MIL" at 12894.46,3515.64 h60
  text "OTHER" at 13391.46,3515.64 h60
  text "X" at 12760,3510 h60
  text "BOARD FINISH:" at 11332.46,3356.64 h60
  text "SILKSCREEN:" at 11487.68,3238.64 h60
  text "X" at 12436.46,3238.64 h60
  text "TOP" at 12562.46,3238.64 h60
  text "BOTTOM" at 13073.46,3238.64 h60
  text "SILKSCREEN COLOR:" at 11487.68,3071.64 h60
  text "X" at 12435.42,3071.64 h60
  text "WHITE" at 12562.46,3071.64 h60
  text "OTHER" at 13073.46,3071.64 h60
  text "SOLDER RESIST COLOR:" at 11487.68,2901.64 h60
  text "X" at 12055.42,2742.44 h60
  text "GREEN" at 12182.46,2742.44 h60
  text "BLUE" at 12773.46,2742.44 h60
  text "OTHER" at 13311.46,2742.44 h60
  text "IMMERSION GOLD (ENIG)" at 12393.46,2553.92 h60
  text "ENEPIG" at 13731,2550.64 h60
  text "SURFACE FINISH:" at 11332.46,2549.64 h60
  text "X" at 12206.51,2549.64 h60
  text "IMM. TIN/SILVER OR EQUIV" at 11662,2392.64 h60
  text "OTHER" at 13093.46,2392.64 h60
  text "ARRAY/PANEL:" at 11332.46,2213.64 h60
  text "CUT AND TRIM PER MECH LAYER 1" at 12393.46,2209.35 h60
  text "N.C. ROUTE" at 12393.46,2057.64 h60
  text "X" at 13072.46,2057.64 h60
  text "V. SCORE" at 13259.46,2057.64 h60
  text "CERTIFICATION:" at 11332.46,1920.64 h60
  text "MATERIALS AND WORKMANSHIP FOR ALL PCBS" at 12057.46,1920.64 h60
  text "TO MEET OR EXCEED THE REQUIREMENTS OF:" at 12057.46,1822.64 h60
  text "X" at 11683.96,1686.13 h60
  text "ANSI IPC-A-600F CLASS ->" at 11822.96,1686.13 h60
  text "X" at 13462.02,1686.13 h60
  text "2" at 13580.96,1686.14 h60
  text "1" at 13265.96,1684.64 h60
  text "3" at 13934.96,1684.64 h60
  text "X" at 11686.02,1526.64 h60
  text "UL 94V-0" at 11822.96,1526.64 h60
  text "X" at 12498.02,1526.64 h60
  text "RoHS" at 12634.96,1526.64 h60
  text "OTHER" at 13279.36,1526.64 h60
  text "PER ORDER" at 13676.42,1526.64 h60
  text "ADDITIONAL REQUIREMENTS:" at 11332.46,1385.64 h60
  text "MICROSECTION:" at 11407.23,1270.64 h60
  text "YES" at 12312.96,1270.64 h60
  text "REQUIRED" at 13174.46,1114.49 h60
  text "BARE BOARD ELEC. TEST:" at 11407.23,1111.64 h60
  text "NONE" at 12712.96,1111.64 h60
  text "X" at 13047.46,1111.64 h60
  text "PER ORDER" at 13766.46,1111.64 h60
  text "MANUFACTURER'S UL:" at 11407.23,954.64 h60
  text "RAIL" at 12572.96,950.35 h60
  text "METAL" at 13064.77,950.35 h60
  text "X" at 13440,950 h60
  text "SILK" at 13576.46,950.35 h60
  text ".Layer_Name" at 577,-858.49 h60
M11 Gerber Information:
  lines w10: -292,-930.17 6308,-930.17 ; -292,-726.83 6310,-726.83 ; -292,-523.5 -292,-1133.5 3713,-1133.5 6310,-1133.5 6310,-523.5 -291.5,-523.5 -291.5,-1133.5 1284,-1133.5 ; 2173,-1133.5 2173,-523.5 ; 3440,-726.83 3440,-523.5 ; 4280,-726.83 4280,-523.5 ; 4902,-1140 4902,-937.17
  text "ALL ARTWORK VIEWED FROM TOP SIDE" at -228.5,-655.67 h60
  text "BOARD #:" at 2248,-655.67 h60
  text ".PRJ_Number" at 2793.5,-655.67 h60
  text "REV:" at 3638,-655.67 h60
  text ".PCB_Rev" at 3929.5,-655.67 h60
  text "SVN REV:" at 4476,-655.67 h60
  text ".VersionControl_RevNumber" at 4982,-655.67 h60
  text "LAYER NAME =" at -228.5,-858.49 h60
  text "TID #:" at 2248,-859 h60
  text ".TID" at 2793.5,-859 h60
  text "PLOT NAME =" at -228.5,-1064.34 h60
  text ".plot_File_Name" at 577,-1064.34 h60
  text "GENERATED    :" at 2250,-1064.34 h60
  text ".Print_Date" at 3119.5,-1064.34 h60
  text ".Print_Time" at 3848.5,-1064.34 h60
  text "TEXAS INSTRUMENTS" at 5113,-1064.34 h60
M12 Stackup:
  drawing of 165 lines, arcs and shapes, not listed
  text "Layer" at 9798.08,7830 h60
  text "Name" at 10207.99,7830 h60
  text "Material" at 11067.76,7830 h60
  text "Thickness" at 11927.52,7830 h60
  text "Constant" at 12577.36,7830 h60
  text "Board Layer Stack" at 13147.22,7830 h60
  text "1" at 9798.08,7710 h60
  text "Top Overlay" at 10207.99,7710 h60
  text "2" at 9798.08,7590 h60
  text "Top Solder" at 10207.99,7590 h60
  text "Solder Resist" at 11067.76,7590 h60
  text "0.40mil" at 11927.52,7590 h60
  text "3.5" at 12577.36,7590 h60
  text "3" at 9798.08,7470 h60
  text "Top Layer" at 10207.99,7470 h60
  text "Copper" at 11067.76,7470 h60
  text "2.80mil" at 11927.52,7470 h60
  text "4" at 9798.08,7350 h60
  text "Dielectric1" at 10207.99,7350 h60
  text "FR-4" at 11067.76,7350 h60
  text "59.20mil" at 11927.52,7350 h60
  text "4.8" at 12577.36,7350 h60
  text "5" at 9798.08,7230 h60
  text "Bottom Layer" at 10207.99,7230 h60
  text "Copper" at 11067.76,7230 h60
  text "2.80mil" at 11927.52,7230 h60
  text "6" at 9798.08,7110 h60
  text "Bottom Solder" at 10207.99,7110 h60
  text "Solder Resist" at 11067.76,7110 h60
  text "0.40mil" at 11927.52,7110 h60
  text "3.5" at 12577.36,7110 h60
  text ".Layer_Name" at 577,-858.49 h60
M13 Component Bodies Top:
  text ".Layer_Name" at 577,-858.49 h60
M14 Component Bodies Bottom:
  text ".Layer_Name" at 577,-858.49 h60
M15 Courtyards Top:
  text ".Layer_Name" at 577,-858.49 h60
M16 Courtyards Bottom:
  text ".Layer_Name" at 577,-858.49 h60
Drill Drawing:
  lines w10: 4056.04,1474.86 4111.23,1474.86 4083.63,1419.67 4056.04,1474.86 ; 4056.04,1571.44 4083.63,1543.84 4111.23,1571.44 4083.63,1599.03 4056.04,1571.44 ; 4056.04,1792.2 4083.63,1805.99 4111.23,1792.2 4097.43,1819.79 4111.23,1847.39 4083.63,1833.59 4056.04,1847.39 4069.83,1819.79 4056.04,1792.2 ; 4056.04,1916.37 4056.04,1930.17 4069.83,1943.97 4056.04,1957.76 4056.04,1971.56 4069.83,1971.56 4083.63,1957.76 4097.43,1971.56 4111.23,1971.56 4111.23,1957.76 4097.43,1943.97 4111.23,1930.17 4111.23,1916.37 4097.43,1916.37 4083.63,1930.17 4069.83,1916.37 4056.04,1916.37 ; 4067.07,1463.82 4100.19,1463.82 4083.63,1430.71 4067.07,1463.82 ; 4067.07,1803.23 4083.63,1811.51 4100.19,1803.23 4091.91,1819.79 4100.19,1836.35 4083.63,1828.07 4067.07,1836.35 4075.35,1819.79 4067.07,1803.23 ; 4067.07,1927.41 4067.07,1935.69 4075.35,1943.97 4067.07,1952.25 4067.07,1960.52 4075.35,1960.52 4083.63,1952.25 4091.91,1960.52 4100.19,1960.52 4100.19,1952.25 4091.91,1943.97 4100.19,1935.69 4100.19,1927.41 4091.91,1927.41 4083.63,1935.69 4075.35,1927.41 4067.07,1927.41
  lines w12: 4006,1382.42 5983.93,1382.42 ; 4006,2375.82 5983.93,2375.82 ; 4343.86,1258.24 4343.86,2500 ; 4675.86,1258.24 4675.86,2500 ; 5312.42,1258.24 5312.42,2500 ; 5571.53,1258.24 5571.53,2500 ; 4006,1258.24 5983.93,1258.24 5983.93,2500 4006,2500 4006,1258.24
  text "Symbol" at 4080.51,2413.08 h72
  text "Quantity" at 4381.11,2413.08 h72
  text "Finished Hole Size" at 4713.12,2413.08 h72
  text "Plated" at 5349.67,2413.08 h72
  text "Hole Type" at 5608.78,2413.08 h72
  text "12" at 4381.11,2288.9 h60
  text "8.00mil (0.203mm)" at 4713.12,2288.9 h60
  text "PTH" at 5349.67,2288.9 h60
  text "Round" at 5608.78,2288.9 h60
  text "C" at 4055.24,2278.91 h55.19
  text "357" at 4381.11,2164.72 h60
  text "10.00mil (0.254mm)" at 4713.12,2164.72 h60
  text "PTH" at 5349.67,2164.72 h60
  text "Round" at 5608.78,2164.72 h60
  text "D" at 4055.24,2154.73 h55.19
  text "91" at 4381.11,2040.55 h60
  text "12.00mil (0.305mm)" at 4713.12,2040.55 h60
  text "PTH" at 5349.67,2040.55 h60
  text "Round" at 5608.78,2040.55 h60
  text "B" at 4055.24,2030.56 h55.19
  text "10" at 4381.11,1916.37 h60
  text "31.00mil (0.787mm)" at 4713.12,1916.37 h60
  text "PTH" at 5349.67,1916.37 h60
  text "Round" at 5608.78,1916.37 h60
  text "4" at 4381.11,1792.2 h60
  text "39.37mil (1.000mm)" at 4713.12,1792.2 h60
  text "PTH" at 5349.67,1792.2 h60
  text "Round" at 5608.78,1792.2 h60
  text "12" at 4381.11,1668.02 h60
  text "40.00mil (1.016mm)" at 4713.12,1668.02 h60
  text "PTH" at 5349.67,1668.02 h60
  text "Round" at 5608.78,1668.02 h60
  text "A" at 4055.24,1658.03 h55.19
  text "20" at 4381.11,1543.84 h60
  text "45.28mil (1.150mm)" at 4713.12,1543.84 h60
  text "PTH" at 5349.67,1543.84 h60
  text "Round" at 5608.78,1543.84 h60
  text "8" at 4381.11,1419.67 h60
  text "51.18mil (1.300mm)" at 4713.12,1419.67 h60
  text "PTH" at 5349.67,1419.67 h60
  text "Round" at 5608.78,1419.67 h60
  text "514 Total" at 4381.11,1295.49 h60
  text ".Layer_Name" at 577,-858.49 h60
